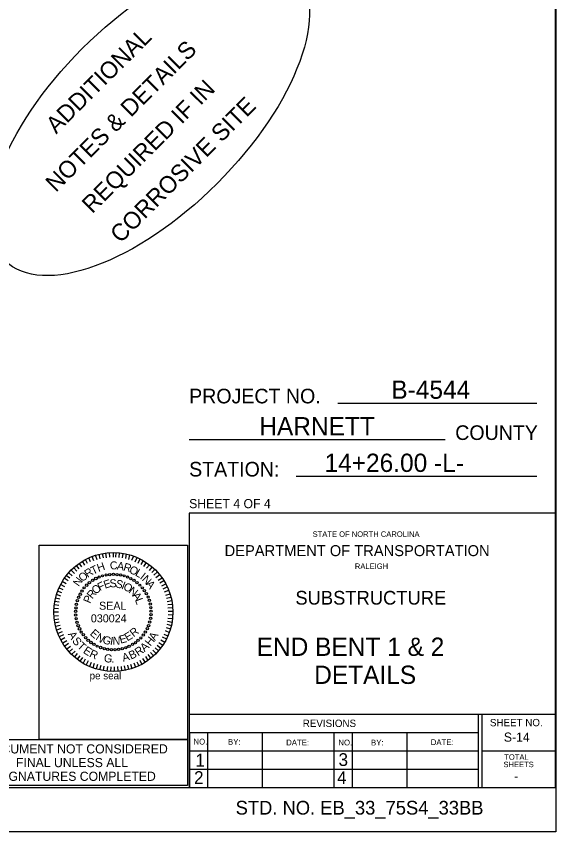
# Model space of a CAD drawing. Extents: x -41 to 191, y -168 to 6.
# Drawn here: x 58.79 to 75.65, y -168.43 to -142.92 of the extents above; entities that cross this region are included whole.
import ezdxf

# ---------------------------------------------------------------- set-up
doc = ezdxf.new("R2010")
doc.units = 0
for name, color, linetype in [('Peseal', 7, 'Continuous'), ('Plan Sheet CELL', 7, 'Continuous'), ('Plot Shape CELL', 7, 'Continuous'), ('Sheet Sticker Exception Certification CELL', 7, 'Continuous'), ('Subtitle Text', 7, 'Continuous'), ('Text', 7, 'Continuous'), ('Title Text', 7, 'Continuous'), ('User Information Notes', 7, 'Continuous'), ('User Information Notes CELL', 7, 'Continuous')]:
    doc.layers.add(name, color=color, linetype=linetype)

msp = doc.modelspace()

# ---------------------------------------------------------------- linework, layer by layer
at = {"layer": 'Peseal'}
for p, q in [((61.015, -160.036), (60.952, -159.911)), ((61.104, -159.991), (61.051, -159.866)), ((61.212, -159.955), (61.158, -159.821)), ((61.31, -159.92), (61.265, -159.776)), ((61.408, -159.893), (61.373, -159.75)), ((61.507, -159.866), (61.48, -159.723)), ((61.605, -159.857), (61.587, -159.714)), ((61.713, -159.839), (61.704, -159.696)), ((61.82, -159.839), (61.82, -159.696)), ((61.9, -159.839), (61.909, -159.696)), ((61.999, -159.848), (62.017, -159.705)), ((62.106, -159.866), (62.124, -159.723)), ((62.205, -159.884), (62.231, -159.741)), ((62.303, -159.911), (62.339, -159.767)), ((62.401, -159.937), (62.455, -159.803)), ((62.5, -159.982), (62.562, -159.848)), ((62.598, -160.027), (62.661, -159.893)), ((60.675, -160.277), (60.585, -160.17)), ((60.755, -160.206), (60.666, -160.098)), ((60.836, -160.143), (60.755, -160.027)), ((60.925, -160.09), (60.854, -159.964)), ((62.688, -160.072), (62.759, -159.946)), ((62.777, -160.134), (62.858, -160.009)), ((62.858, -160.188), (62.947, -160.081)), ((62.947, -160.259), (63.036, -160.152)), ((60.46, -160.501), (60.353, -160.42)), ((60.532, -160.42), (60.424, -160.331)), ((60.603, -160.349), (60.496, -160.242)), ((63.019, -160.322), (63.117, -160.224)), ((63.09, -160.403), (63.198, -160.304)), ((63.153, -160.474), (63.269, -160.385)), ((60.299, -160.769), (60.165, -160.698)), ((60.344, -160.671), (60.219, -160.599)), ((60.407, -160.582), (60.281, -160.501)), ((63.224, -160.564), (63.341, -160.483)), ((63.278, -160.644), (63.394, -160.573)), ((63.332, -160.734), (63.457, -160.671)), ((60.21, -160.957), (60.076, -160.904)), ((60.254, -160.859), (60.12, -160.796)), ((63.376, -160.832), (63.502, -160.769)), ((63.421, -160.93), (63.555, -160.877)), ((60.147, -161.154), (60.013, -161.118)), ((60.174, -161.056), (60.04, -161.011)), ((63.457, -161.029), (63.591, -160.984)), ((63.484, -161.127), (63.618, -161.091)), ((63.502, -161.226), (63.645, -161.199)), ((60.102, -161.458), (59.959, -161.449)), ((60.111, -161.351), (59.977, -161.333)), ((60.129, -161.252), (59.986, -161.226)), ((63.52, -161.324), (63.663, -161.306)), ((63.528, -161.422), (63.672, -161.413)), ((60.102, -161.566), (59.959, -161.566)), ((60.102, -161.673), (59.959, -161.682)), ((63.537, -161.53), (63.681, -161.53)), ((63.537, -161.637), (63.681, -161.646)), ((60.12, -161.78), (59.977, -161.798)), ((60.129, -161.879), (59.995, -161.905)), ((60.156, -161.977), (60.013, -162.013)), ((63.493, -161.941), (63.636, -161.977)), ((63.511, -161.843), (63.654, -161.87)), ((63.528, -161.744), (63.672, -161.762)), ((60.183, -162.075), (60.049, -162.12)), ((60.219, -162.174), (60.085, -162.227)), ((63.439, -162.138), (63.573, -162.192)), ((63.466, -162.04), (63.609, -162.084)), ((60.263, -162.272), (60.129, -162.335)), ((60.308, -162.362), (60.174, -162.433)), ((60.362, -162.46), (60.237, -162.532)), ((63.305, -162.424), (63.43, -162.496)), ((63.35, -162.335), (63.484, -162.397)), ((63.394, -162.245), (63.528, -162.299)), ((60.415, -162.541), (60.299, -162.621)), ((60.478, -162.63), (60.362, -162.719)), ((60.541, -162.711), (60.442, -162.8)), ((63.126, -162.675), (63.233, -162.773)), ((63.189, -162.594), (63.305, -162.684)), ((63.242, -162.514), (63.367, -162.594)), ((60.621, -162.782), (60.514, -162.889)), ((60.693, -162.854), (60.603, -162.961)), ((60.773, -162.925), (60.693, -163.033)), ((60.854, -162.979), (60.773, -163.095)), ((62.822, -162.952), (62.902, -163.068)), ((62.902, -162.889), (62.992, -163.006)), ((62.983, -162.827), (63.072, -162.925)), ((63.054, -162.746), (63.162, -162.854)), ((60.943, -163.033), (60.872, -163.158)), ((61.033, -163.086), (60.97, -163.211)), ((61.122, -163.131), (61.069, -163.256)), ((61.221, -163.167), (61.176, -163.301)), ((61.328, -163.203), (61.283, -163.337)), ((61.426, -163.229), (61.391, -163.364)), ((61.525, -163.247), (61.498, -163.39)), ((62.16, -163.238), (62.187, -163.381)), ((62.258, -163.22), (62.294, -163.355)), ((62.357, -163.185), (62.401, -163.328)), ((62.455, -163.149), (62.509, -163.283)), ((62.553, -163.113), (62.616, -163.238)), ((62.643, -163.059), (62.714, -163.194)), ((62.732, -163.006), (62.813, -163.131)), ((61.632, -163.265), (61.614, -163.408)), ((61.739, -163.274), (61.73, -163.417)), ((61.847, -163.274), (61.847, -163.417)), ((61.954, -163.265), (61.963, -163.408)), ((62.061, -163.256), (62.079, -163.399))]:
    msp.add_line(p, q, dxfattribs=at)
for centre, radius in [((61.377, -160.461), 0.0341), ((61.48, -160.425), 0.0326), ((61.592, -160.398), 0.0316), ((61.708, -160.385), 0.0361), ((61.82, -160.376), 0.0358), ((61.932, -160.385), 0.0361), ((62.044, -160.394), 0.0369), ((62.16, -160.425), 0.0326), ((62.263, -160.461), 0.0341), ((60.988, -160.716), 0.038), ((61.073, -160.64), 0.0385), ((61.171, -160.568), 0.0385), ((61.274, -160.51), 0.04), ((62.366, -160.514), 0.0361), ((62.464, -160.568), 0.0361), ((62.558, -160.635), 0.0349), ((62.647, -160.716), 0.0349), ((60.84, -160.899), 0.0385), ((60.903, -160.801), 0.0316), ((62.723, -160.801), 0.0349), ((62.79, -160.886), 0.0361), ((62.853, -160.984), 0.0361), ((60.693, -161.203), 0.0382), ((60.733, -161.096), 0.0341), ((60.787, -161.002), 0.0412), ((62.907, -161.087), 0.0341), ((62.947, -161.194), 0.0382), ((60.648, -161.427), 0.0361), ((60.666, -161.315), 0.0369), ((62.974, -161.306), 0.0369), ((62.992, -161.418), 0.0361), ((60.639, -161.539), 0.0358), ((60.639, -161.65), 0.0361), ((62.983, -161.758), 0.0361), ((63.001, -161.53), 0.0358), ((63.001, -161.642), 0.0361), ((60.657, -161.767), 0.0361), ((60.684, -161.879), 0.0369), ((60.72, -161.981), 0.0382), ((62.92, -161.981), 0.0382), ((62.956, -161.87), 0.0369), ((60.764, -162.084), 0.04), ((60.814, -162.183), 0.0361), ((60.881, -162.268), 0.0349), ((62.817, -162.183), 0.0361), ((62.88, -162.075), 0.0361), ((60.952, -162.362), 0.038), ((61.033, -162.442), 0.038), ((61.118, -162.509), 0.0385), ((62.513, -162.514), 0.0349), ((62.594, -162.442), 0.0349), ((62.679, -162.366), 0.0349), ((62.755, -162.277), 0.0385), ((61.212, -162.572), 0.0361), ((61.314, -162.626), 0.0341), ((61.422, -162.666), 0.0382), ((61.534, -162.702), 0.0369), ((61.645, -162.728), 0.0361), ((61.757, -162.737), 0.0358), ((61.874, -162.737), 0.0358), ((61.985, -162.728), 0.0361), ((62.097, -162.702), 0.0369), ((62.209, -162.67), 0.0341), ((62.312, -162.63), 0.04), ((62.419, -162.572), 0.0361)]:
    msp.add_circle(centre, radius, dxfattribs=at)
at = {"layer": 'Plan Sheet CELL'}
for p, q in [((75.628, -118.994), (75.628, -167.042)), ((75.057, -155.029), (68.84, -155.029)), ((72.197, -156.174), (64.189, -156.174)), ((75.057, -157.317), (67.53, -157.317)), ((75.628, -158.461), (64.189, -158.461)), ((64.189, -158.461), (64.189, -167.042)), ((64.189, -164.753), (75.628, -164.753)), ((73.227, -164.753), (73.227, -167.042)), ((73.341, -164.753), (73.341, -167.042)), ((64.189, -165.325), (73.231, -165.325)), ((64.196, -165.325), (64.196, -167.042)), ((64.76, -165.325), (64.76, -167.042)), ((66.476, -165.335), (66.476, -167.05)), ((68.709, -165.325), (68.709, -167.056)), ((69.282, -165.325), (69.282, -167.043)), ((70.998, -165.325), (70.998, -167.043)), ((64.189, -165.897), (73.25, -165.897)), ((73.341, -165.897), (75.608, -165.897)), ((64.189, -166.469), (73.231, -166.469)), ((2.412, -167.042), (75.628, -167.042)), ((75.648, -168.429), (75.648, -168.429))]:
    msp.add_line(p, q, dxfattribs=at)
at = {"layer": 'Plot Shape CELL'}
msp.add_lwpolyline([(0, -118.093), (75.648, -118.093), (75.648, -168.429), (0, -168.429)], close=True, dxfattribs=at)
at = {"layer": 'Sheet Sticker Exception Certification CELL'}
msp.add_lwpolyline([(57.615, -165.549), (64.139, -165.549), (64.139, -166.985), (57.615, -166.985)], close=True, dxfattribs=at)
at = {"layer": 'User Information Notes'}
msp.add_line((61.82, -161.557), (61.82, -161.557), dxfattribs=at)
msp.add_ellipse((62.956, -146.039), major_axis=(4.526, 4.526), ratio=0.46622, dxfattribs=at)
at = {"layer": 'User Information Notes CELL'}
msp.add_line((61.82, -161.557), (61.82, -161.557), dxfattribs=at)
msp.add_lwpolyline([(59.501, -159.467), (64.139, -159.467), (64.139, -165.549), (59.501, -165.549)], close=True, dxfattribs=at)
msp.add_circle((61.82, -161.557), 1.861, dxfattribs=at)

# ---------------------------------------------------------------- texts
at = {"layer": 'Peseal'}
for s, height, rotation, p in [('R', 0.25, 32.9699, (61.015, -160.492)), ('T', 0.25, 25.943, (61.185, -160.394)), ('H', 0.25, 18.9162, (61.355, -160.304)), ('C', 0.25, 4.8625, (61.722, -160.233)), ('A', 0.25, 350.8088, (61.918, -160.224)), ('R', 0.25, 343.7819, (62.115, -160.251)), ('O', 0.25, 336.7551, (62.294, -160.322)), ('O', 0.25, 39.9967, (60.854, -160.626)), ('L', 0.25, 329.7282, (62.482, -160.403)), ('I', 0.25, 322.7014, (62.634, -160.501)), ('N', 0.25, 315.6745, (62.697, -160.555)), ('N', 0.25, 54.0504, (60.738, -160.778)), ('F', 0.25, 26.4777, (61.399, -160.904)), ('E', 0.25, 18.4448, (61.56, -160.832)), ('S', 0.25, 2.3789, (61.704, -160.787)), ('S', 0.25, 346.313, (61.874, -160.778)), ('I', 0.25, 338.28, (62.052, -160.823)), ('O', 0.25, 330.2471, (62.106, -160.832)), ('A', 0.25, 308.6477, (62.822, -160.689)), ('R', 0.25, 50.5765, (61.158, -161.163)), ('O', 0.25, 42.5436, (61.274, -161.02)), ('N', 0.25, 322.2141, (62.276, -160.939)), ('P', 0.25, 66.6424, (61.095, -161.306)), ('A', 0.25, 306.1483, (62.401, -161.047)), ('L', 0.25, 290.0824, (62.491, -161.172)), ('A', 0.254, 300.3993, (60.389, -162.251)), ('E', 0.25, 318.5179, (61.069, -162.254)), ('N', 0.25, 326.5361, (61.247, -162.406)), ('E', 0.25, 30.6815, (62.258, -162.478)), ('R', 0.25, 38.6997, (62.455, -162.353)), ('A', 0.254, 59.6007, (63.124, -162.467)), ('S', 0.254, 309.4349, (60.516, -162.467)), ('T', 0.254, 318.1096, (60.668, -162.653)), ('G', 0.25, 342.5725, (61.462, -162.523)), ('I', 0.25, 350.5906, (61.704, -162.576)), ('N', 0.25, 358.6088, (61.793, -162.576)), ('E', 0.25, 14.6452, (62.044, -162.549)), ('H', 0.254, 51.3597, (62.98, -162.644)), ('E', 0.254, 327.1453, (60.855, -162.821)), ('R', 0.254, 335.458, (61.048, -162.947)), ('B', 0.254, 24.8312, (62.372, -163.048)), ('R', 0.254, 33.5776, (62.593, -162.947)), ('A', 0.254, 42.3241, (62.795, -162.813)), ('G', 0.254, 353.3858, (61.513, -163.117)), ('A', 0.254, 15.7955, (62.131, -163.116)), ('.', 0.254, 2.1323, (61.754, -163.145))]:
    msp.add_text(s, height=height, rotation=rotation, dxfattribs=at).set_placement(p)
for s, p in [('SEAL', (61.373, -161.485)), ('030024', (61.116, -161.879))]:
    msp.add_text(s, height=0.2505, dxfattribs=at).set_placement(p)
at = {"layer": 'Plan Sheet CELL'}
for s, height, p in [('PROJECT NO.', 0.4576, (64.189, -155.029)), ('COUNTY', 0.4576, (72.508, -156.174)), ('STATION:', 0.4576, (64.189, -157.317)), ('SHEET 4 OF 4', 0.286, (64.189, -158.308)), ('STATE OF NORTH CAROLINA', 0.17159, (68.049, -159.205)), ('DEPARTMENT OF TRANSPORTATION', 0.34319, (65.298, -159.808)), ('RALEIGH', 0.1716, (69.37, -160.21)), ('REVISIONS', 0.2288, (67.741, -165.152)), ('SHEET NO.', 0.2288, (73.593, -165.13)), ('NO.', 0.1823, (64.325, -165.702)), ('BY:', 0.1823, (65.405, -165.71)), ('DATE:', 0.1823, (67.222, -165.73)), ('NO.', 0.1823, (68.855, -165.73)), ('BY:', 0.1823, (69.876, -165.732)), ('DATE:', 0.1823, (71.742, -165.72)), ('1', 0.4, (64.384, -166.392)), ('3', 0.4, (68.859, -166.373)), ('TOTAL', 0.1716, (74.041, -166.179)), ('SHEETS', 0.1716, (74.015, -166.41)), ('2', 0.4, (64.343, -166.936)), ('4', 0.4, (68.816, -166.936))]:
    msp.add_text(s, height=height, dxfattribs=at).set_placement(p)
at = {"layer": 'Sheet Sticker Exception Certification CELL'}
for s, p in [('DOCUMENT NOT CONSIDERED', (57.75, -165.981)), ('FINAL UNLESS ALL', (58.776, -166.409)), ('SIGNATURES COMPLETED', (58.181, -166.838))]:
    msp.add_text(s, height=0.28561, dxfattribs=at).set_placement(p)
at = {"layer": 'Subtitle Text'}
for s, p in [('SUBSTRUCTURE', (67.511, -161.325)), ('STD. NO. EB_33_75S4_33BB', (65.643, -167.893))]:
    msp.add_text(s, height=0.429, dxfattribs=at).set_placement(p)
at = {"layer": 'Text'}
for s, p in [('S-14', (74.028, -165.613)), ('-', (74.347, -166.835))]:
    msp.add_text(s, height=0.286, dxfattribs=at).set_placement(p)
at = {"layer": 'Title Text'}
for s, p in [('B-4544', (70.51, -154.886)), ('HARNETT', (66.382, -156.031)), ('14+26.00 -L-', (68.422, -157.174)), ('END BENT 1 & 2', (66.301, -162.929)), ('DETAILS', (68.098, -163.806))]:
    msp.add_text(s, height=0.572, dxfattribs=at).set_placement(p)
at = {"layer": 'User Information Notes'}
for s, height, p in [('ADDITIONAL', 0.5316, (60.034, -146.625)), ('NOTES & DETAILS', 0.53163, (60.021, -148.446)), ('REQUIRED IF IN', 0.53163, (61.16, -149.115)), ('CORROSIVE SITE', 0.53163, (62.043, -150.042))]:
    msp.add_text(s, height=height, rotation=45, dxfattribs=at).set_placement(p)
at = {"layer": 'User Information Notes CELL'}
msp.add_text('pe seal', height=0.229, dxfattribs=at).set_placement((61.078, -163.662))

doc.saveas('drawing.dxf')
